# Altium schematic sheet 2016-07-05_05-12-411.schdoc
size 464 x 212 mm; SheetNumber: 1; SheetTotal: 1
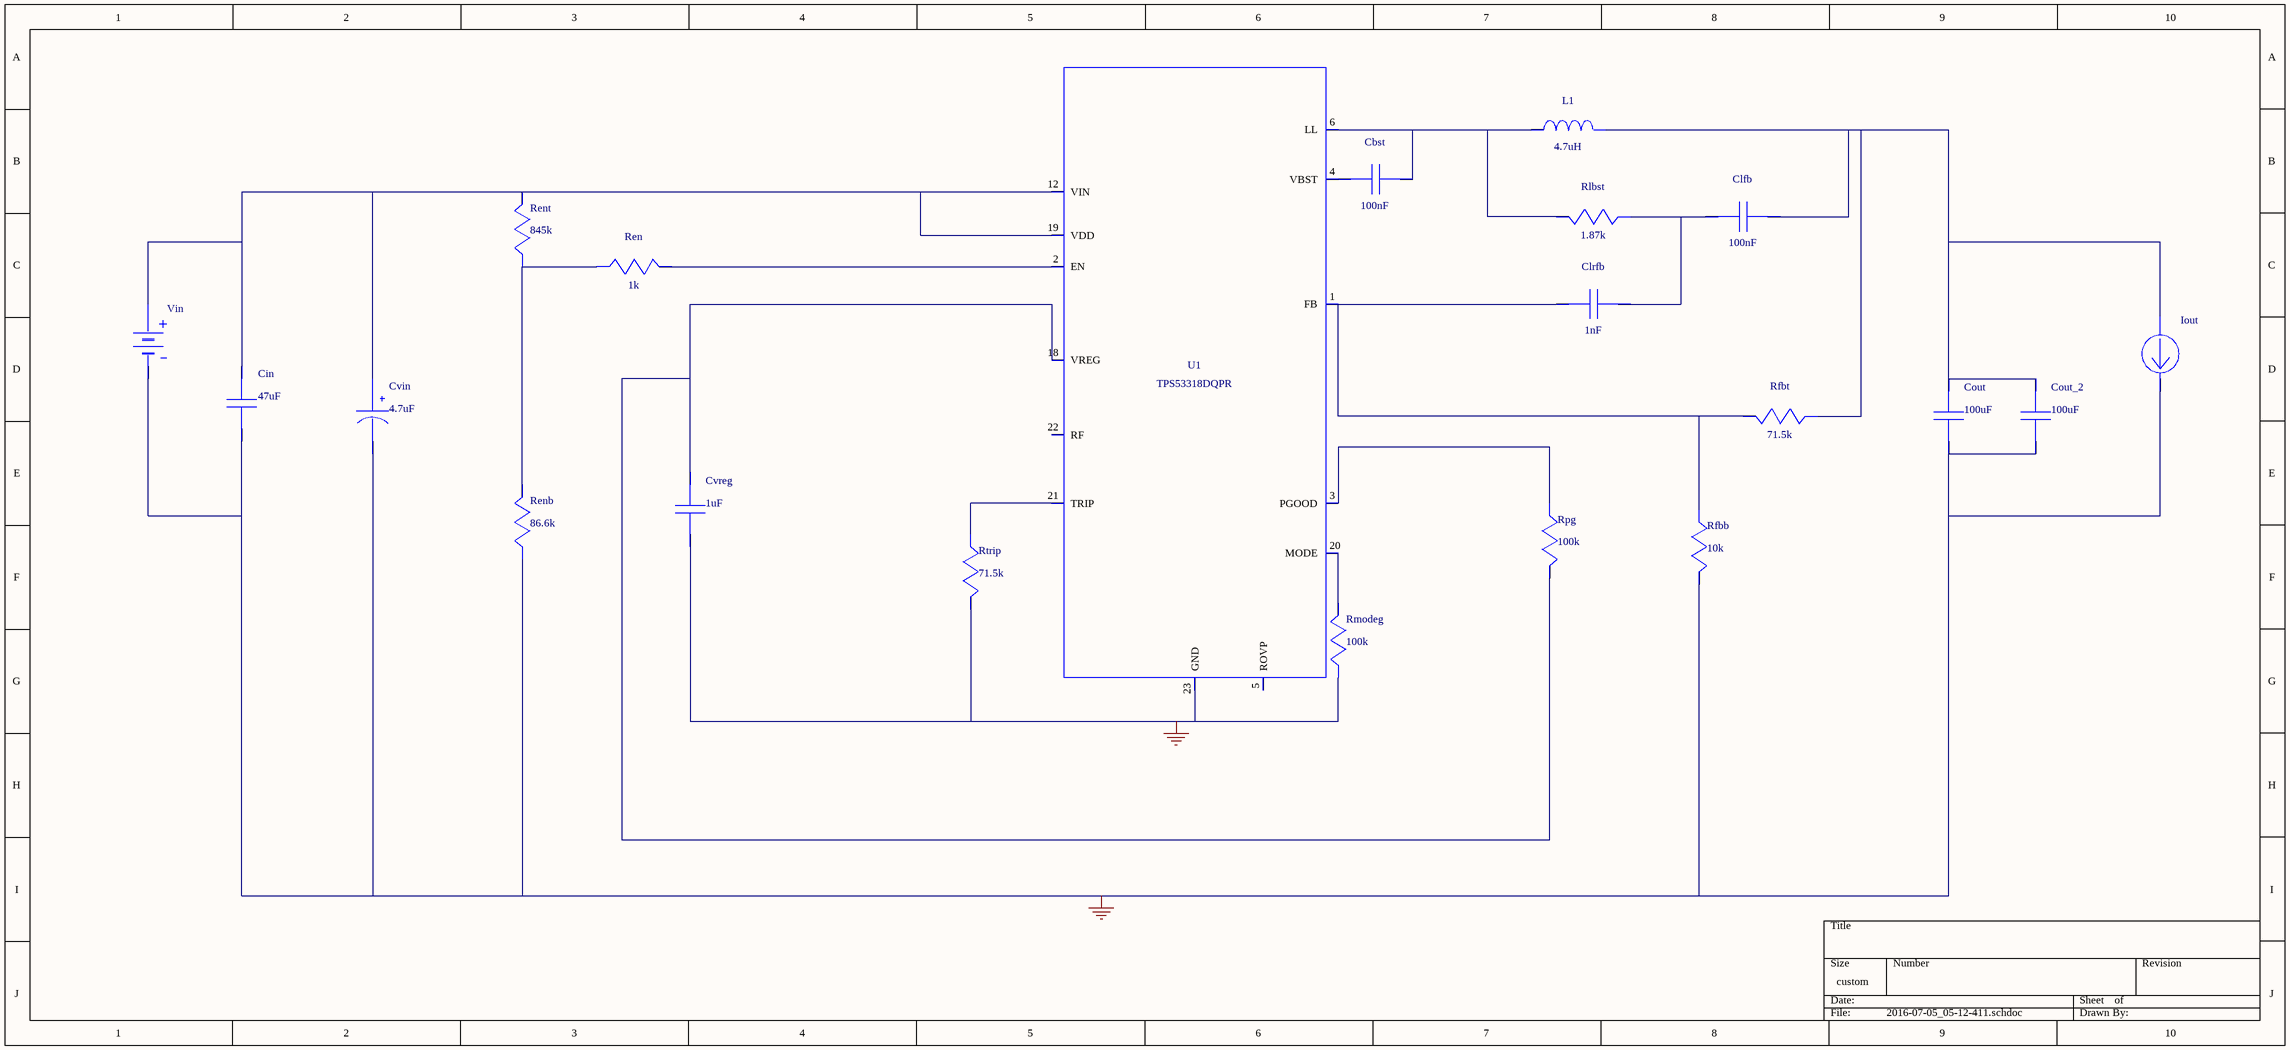
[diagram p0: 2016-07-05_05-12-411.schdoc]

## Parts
Cbst  value 100nF  (hidden comment: C0805C104K5RACTU)
Cin  value 47uF  (hidden comment: C3216X5R1E476M160AC)
Clfb  value 100nF  (hidden comment: C0805C104K5RACTU)
Clrfb  value 1nF  (hidden comment: C0805C102J5GACTU)
Cout  value 100uF  (hidden comment: GRM31CR60J107ME39L)
Cout_2  value 100uF  (hidden comment: GRM31CR60J107ME39L)
Cvin  value 4.7uF  (hidden comment: EMVY350ADA4R7MD55G)
Cvreg  value 1uF  (hidden comment: GRM188R61E105KA12D)
Iout  WB_CURRENT_LOAD  (value not drawn)
L1  value 4.7uH  (hidden comment: XAL6060-472MEB)
Ren  value 1k  (hidden comment: CRCW04021K00FKED)
Renb  value 86.6k  (hidden comment: CRCW040286K6FKED)
Rent  value 845k  (hidden comment: CRCW0402845KFKED)
Rfbb  value 10k  (hidden comment: CRCW040210K0FKED)
Rfbt  value 71.5k  (hidden comment: CRCW040271K5FKED)
Rlbst  value 1.87k  (hidden comment: CRCW04021K87FKED)
Rmodeg  value 100k  (hidden comment: CRCW0402100KFKED)
Rpg  value 100k  (hidden comment: CRCW0402100KFKED)
Rtrip  value 71.5k  (hidden comment: CRCW040271K5FKED)
U1  TPS53318DQPR
Vin  WB_BATTERY  (value not drawn)

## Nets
0: Cin.2 Cout.2 Cout_2.2 Cvin.2(-) Cvreg.2 Iout.2(-) Renb.2 Rfbb.1 Rmodeg.2 Rtrip.1 U1.23(GND) Vin.2(-)
NetCbst_1: Cbst.1 U1.4(VBST)
NetCbst_2: Cbst.2 L1.1 Rlbst.1 U1.6(LL) U1.7(LL) U1.8(LL) U1.9(LL) U1.10(LL) U1.11(LL)
NetCin_1: Cin.1 Cvin.1(+) Rent.1 U1.12(VIN) U1.13(VIN) U1.14(VIN) U1.15(VIN) U1.16(VIN) U1.17(VIN) U1.19(VDD) Vin.1(+)
NetClfb_1: Clfb.1 Clrfb.2 Rlbst.2
NetClfb_2: Clfb.2 Cout.1 Cout_2.1 Iout.1(+) L1.2 Rfbt.2
NetClrfb_1: Clrfb.1 Rfbb.2 Rfbt.1 U1.1(FB)
NetCvreg_1: Cvreg.1 Rpg.1 U1.18(VREG)
NetRen_1: Ren.1 U1.2(EN)
NetRen_2: Ren.2 Renb.1 Rent.2
NetRmodeg_1: Rmodeg.1 U1.20(MODE)
NetRpg_2: Rpg.2 U1.3(PGOOD)
NetRtrip_2: Rtrip.2 U1.21(TRIP)

Not connected (* = marked no-connect by the designer): U1 5(ROVP) 22(RF)

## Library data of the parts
Cbst Clfb = C0805C104K5RACTU: Manufacturer Name: Kemet
Cin = C3216X5R1E476M160AC: C3216X5R1E476M16; Manufacturer Name: TDK
Clrfb = C0805C102J5GACTU: Manufacturer Name: Kemet
Cout Cout_2 = GRM31CR60J107ME39L: GRM31CR60J107ME3; Manufacturer Name: MuRata
Cvin = EMVY350ADA4R7MD55G: EMVY350ADA4R7MD5; Manufacturer Name: Chemi-Con
Cvreg = GRM188R61E105KA12D: GRM188R61E105KA1; Manufacturer Name: MuRata
L1 = XAL6060-472MEB: Manufacturer Name: Coilcraft
Ren = CRCW04021K00FKED: Manufacturer Name: Vishay-Dale
Renb = CRCW040286K6FKED: Manufacturer Name: Vishay-Dale
Rent = CRCW0402845KFKED: Manufacturer Name: Vishay-Dale
Rfbb = CRCW040210K0FKED: Manufacturer Name: Vishay-Dale
Rfbt Rtrip = CRCW040271K5FKED: Manufacturer Name: Vishay-Dale
Rlbst = CRCW04021K87FKED: Manufacturer Name: Vishay-Dale
Rmodeg Rpg = CRCW0402100KFKED: Manufacturer Name: Vishay-Dale
U1 = TPS53318DQPR: Manufacturer Name: Texas Instruments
